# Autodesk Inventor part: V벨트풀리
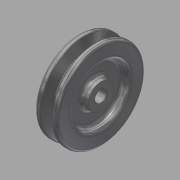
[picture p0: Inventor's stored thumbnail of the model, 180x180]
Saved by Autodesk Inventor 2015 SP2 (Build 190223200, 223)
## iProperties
Created: 2015-11
Part Number: V벨트풀리
Material: 강철, 탄소
Document SubType Name: Modeling
Designer: mduedu
Density: 1 g/cm^3
Appearance: 반광택
Author: mduedu
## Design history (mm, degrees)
sketch "스케치1"
  geometry: L1 (-9.5, 0)-(9.5, 0); L2 (0, 0)-(0, 37.7); L3 (-4.825, 37.7)-(-9.5, 37.7); L4 (-9.5, 37.7)-(-9.5, 0); L5 (0, 28.7)-(-2.074, 28.7); L6 (-2.074, 28.7)-(-4.825, 37.7); L7 (4.825, 37.7)-(9.5, 37.7); L8 (9.5, 37.7)-(9.5, 0); L9 (0, 28.7)-(2.074, 28.7); L10 (2.074, 28.7)-(4.825, 37.7); L11 (-9.5, 35)-(9.5, 35); 3 further points
  constraints: 22 end point, 7 point on line, 4 perpendicular, 3 symmetric about line, 1 coincident, 1 horizontal, 1 horizontal alignment, 1 midpoint, 1 vertical
  dimensions: "d0" = 19 distance of L1.start L1.end; "d2" = 75.4 diameter of L2.end L1 (derived); "d3" = 34 deg angle of L10 L6; "d4" = 6.3 distance between parallel lines of L11 L9; "d5" = 2.7 distance between parallel lines of L7 L11; "d6" = 8 distance of point (4, 35) point (-4, 35); "d7" = 70 diameter of L11 L1
revolve "회전1" sketch "스케치1" stored, may be unused: angle "d8" = 90 deg
sketch "스케치2"
  geometry: C1 r 24 at (0, 0); C2 r 11 at (0, 0); 1 further point
  constraints: 2 centre point, 2 coincident
  dimensions: "d9" = 48 diameter of C1; "d10" = 22 diameter of C2
extrude "돌출1" cut sketch "스케치2" distance "d11" = 6; taper "d12" = 0 deg
fillet "모깎기1" dims "d13" = 3
fillet "모깎기2" dims "d14" = 3
fillet "모깎기3" dims "d15" = 1, "d16" = 0.5, "d17" = 2
hole "구멍1" diameter "d20" = 10; stored, may be unused: countersink angle "d24" = 90 deg, drill point angle "d26" = 118 deg; dims "d18" = 10, "d19" = 10, "d21" = 6, "d22" = 4, "d23" = 2, "d25" = 8
sketch "스케치3"
  geometry: L1 (-1.5, 0)-(1.5, 0); L2 (1.5, 0)-(1.5, 6.4); L3 (1.5, 6.4)-(-1.5, 6.4); L4 (-1.5, 6.4)-(-1.5, 0); 2 further points
  constraints: 8 end point, 2 parallel, 1 coincident, 1 horizontal, 1 midpoint, 1 perpendicular
  dimensions: "d27" = 3 distance of L2.end L3.end; "d29" = 6.4 distance of L3.end L1.start
extrude "돌출2" cut sketch "스케치3" stored distance "d30" = 6; taper "d31" = 0 deg
chamfer "모따기1" distance "d32" = 0.5; stored, may be unused: second distance "d33" = 2, angle "d34" = 45 deg
node "솔리드1"
mirror "대칭1"
